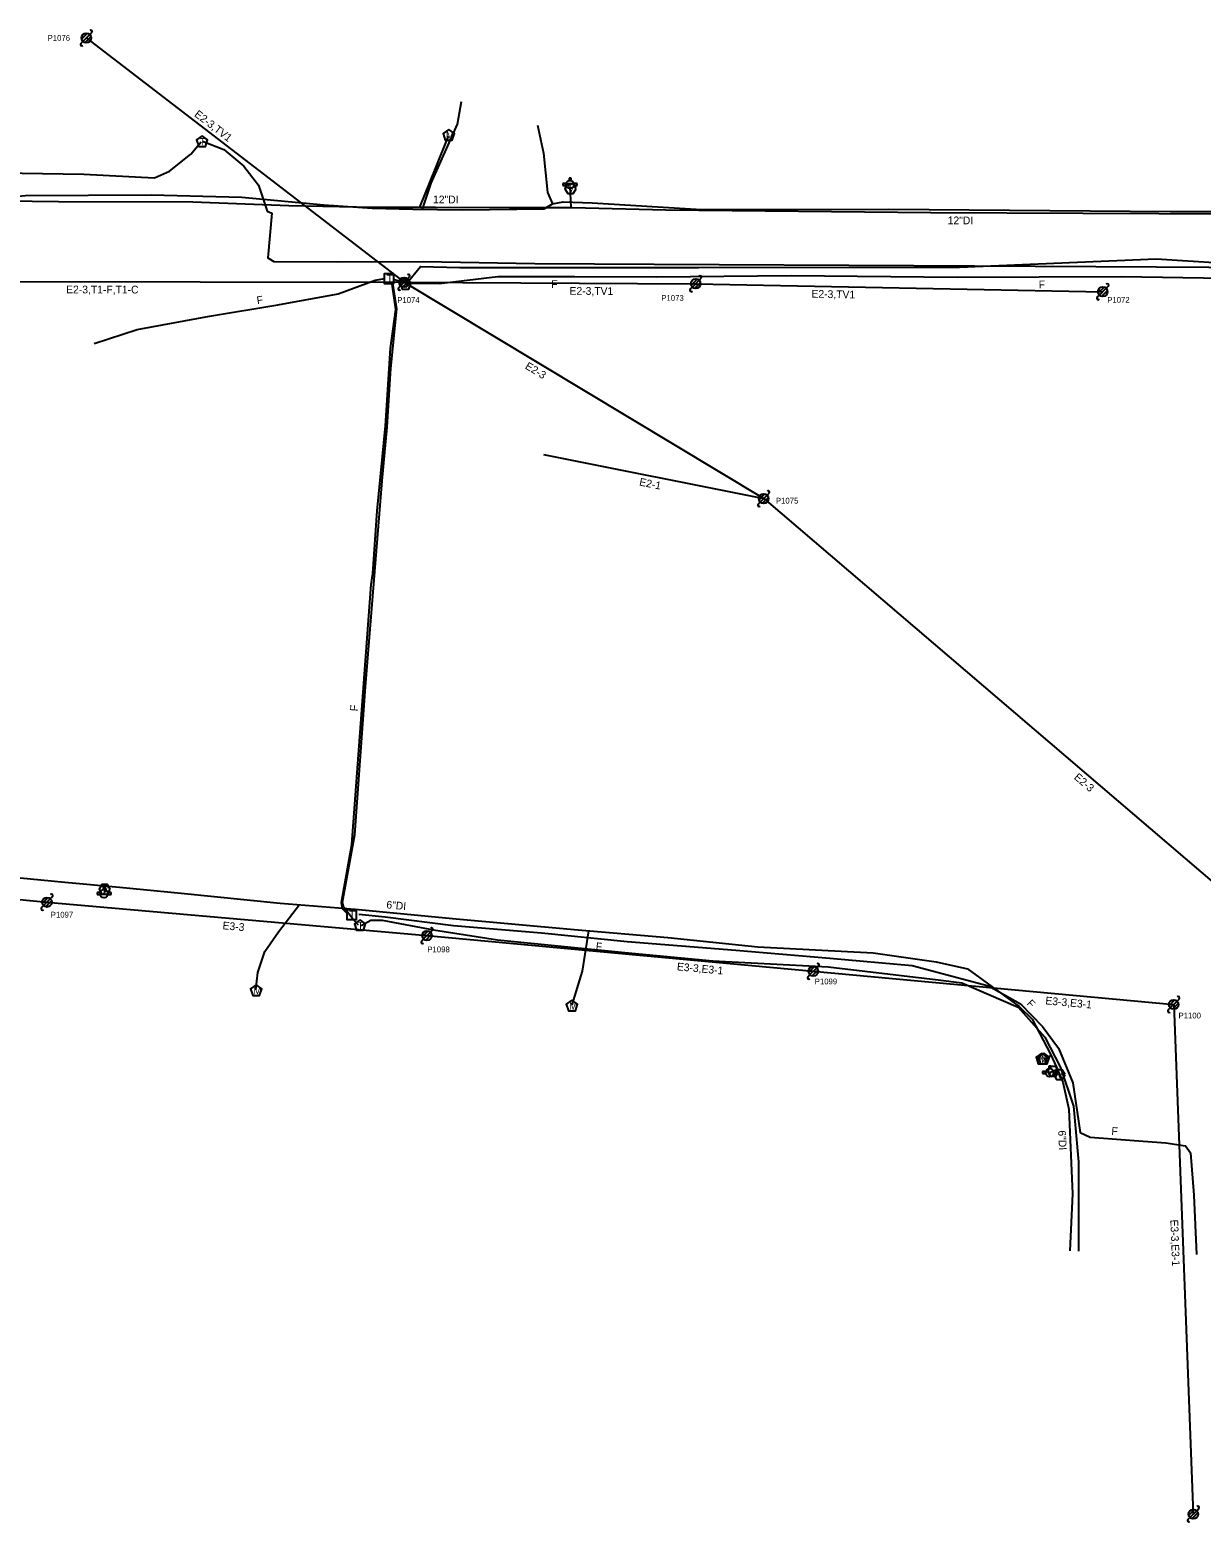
# Model space of a CAD drawing. Extents: x 1741604 to 1825760, y 1164229 to 1194908.
# Drawn here: x 1801773 to 1802379, y 1187603 to 1188375 of the extents above; entities that cross this region are included whole.
import ezdxf

# ---------------------------------------------------------------- set-up
doc = ezdxf.new("R2010")
doc.units = 0
for name, color, linetype in [('RD_EX_SU_Gas', 7, 'Continuous'), ('RD_EX_SU_H2O', 7, 'Continuous'), ('RD_EX_SU_Ovhd', 7, 'Continuous'), ('RD_EX_SU_Pole', 7, 'Continuous'), ('RD_EX_SU_Telecom', 7, 'Continuous'), ('RD_EX_SU_TX_H2O', 7, 'Continuous'), ('RD_EX_SU_TX_Pole', 7, 'Continuous'), ('RD_EX_SU_TX_Telecom', 7, 'Continuous')]:
    doc.layers.add(name, color=color, linetype=linetype)

# ---------------------------------------------------------------- blocks, each defined once
blk = doc.blocks.new('SUE_TPP')
at = {"layer": 'RD_EX_SU_Telecom'}
blk.add_lwpolyline([(0, 3), (-2.85, 0.93), (-1.76, -2.43), (1.76, -2.43), (2.85, 0.93)], close=True, dxfattribs=at)
blk.add_text('T', height=3.75, dxfattribs=at).set_placement((-1.25, -1.88))
blk = doc.blocks.new('SUE_WM')
at = {"layer": 'RD_EX_SU_H2O'}
blk.add_lwpolyline([(0, 3.05), (-2.9, 0.94), (-1.79, -2.47), (1.79, -2.47), (2.9, 0.94)], close=True, dxfattribs=at)
blk.add_text('M', height=3.75, dxfattribs=at).set_placement((-1.43, -1.88))
blk = doc.blocks.new('SUE_WV')
at = {"layer": 'RD_EX_SU_H2O'}
blk.add_lwpolyline([(2.89, 0), (1.44, 2.5), (-1.44, 2.5), (-2.89, 0), (-1.44, -2.5), (1.44, -2.5)], close=True, dxfattribs=at)
blk.add_text('V', height=3.75, dxfattribs=at).set_placement((-1.43, -1.88))
blk = doc.blocks.new('SUE_WFH')
at = {"layer": 'RD_EX_SU_H2O'}
for p, q in [((-2.01, 0.6), (-3.65, 0.6)), ((-3.65, 0.6), (-3.65, -0.45)), ((-0.48, 3.38), (-0.48, 2.04)), ((0.57, 3.38), (-0.48, 3.38)), ((0.57, 2.02), (0.57, 3.38)), ((3.7, 0.6), (2.01, 0.6)), ((3.7, -0.45), (3.7, 0.6)), ((-3.65, -0.45), (-2.05, -0.45)), ((2.05, -0.45), (3.7, -0.45))]:
    blk.add_line(p, q, dxfattribs=at)
for radius in [2.1, 0.263]:
    blk.add_circle((0, 0), radius, dxfattribs=at)
for start, end in [(163.3387, 192.31502), (74.24552, 103.21276), (347.68498, 16.6613)]:
    blk.add_arc((0, 0), 2.1, start, end, dxfattribs=at)
blk = doc.blocks.new('SUE_THH')
at = {"layer": 'RD_EX_SU_Telecom'}
blk.add_lwpolyline([(2.5, 2.5), (-2.5, 2.5), (-2.5, -2.5), (2.5, -2.5)], close=True, dxfattribs=at)
blk.add_text('T', height=4, dxfattribs=at).set_placement((-1.34, -2))
blk = doc.blocks.new('SUE_PP')
at = {"layer": 'RD_EX_SU_Pole'}
for p, q in [((-2.41, -0.65), (0.65, 2.41)), ((-1.77, -1.77), (1.77, 1.77)), ((-0.65, -2.41), (2.41, 0.65)), ((1.77, 1.77), (2.83, 2.83)), ((-2.83, -2.83), (-1.77, -1.77))]:
    blk.add_line(p, q, dxfattribs=at)
blk.add_circle((0, 0), 2.5, dxfattribs=at)
for centre, start, end in [((2.3, 3.36), 315, 135), ((-2.3, -3.36), 135, 315)]:
    blk.add_arc(centre, 0.75, start, end, dxfattribs=at)

msp = doc.modelspace()

# ---------------------------------------------------------------- linework, layer by layer
at = {"layer": 'RD_EX_SU_Gas'}
for points in [[(1801976.25, 1188282.13), (1801980.73, 1188295.55), (1801994.29, 1188326.19), (1801996.46, 1188337.93)], [(1802035.69, 1188325.53), (1802038.75, 1188311.1), (1802040.95, 1188290.73), (1802043.42, 1188284.85), (1802048.92, 1188285.96), (1802064.02, 1188285.5), (1802120.55, 1188282.05), (1802217.43, 1188282.09), (1802363.14, 1188281), (1802531.2, 1188280.89), (1802592.84, 1188280.65), (1802657.49, 1188281.38), (1802745.41, 1188285.57)], [(1801300.18, 1188289.75), (1801395.65, 1188290.16), (1801455.8, 1188291.53), (1801513.04, 1188289.66), (1801598.92, 1188288.81), (1801632.69, 1188288.87), (1801670.37, 1188289.16), (1801709.24, 1188288.32), (1801749.77, 1188287.36), (1801770.8, 1188289.23), (1801835.8, 1188289.57), (1801882.8, 1188288.37), (1801925.16, 1188284.33), (1801950.2, 1188282.64), (1801971.28, 1188282.21), (1801996.82, 1188281.83), (1802039.19, 1188282.29), (1802043.42, 1188284.85)]]:
    msp.add_lwpolyline(points, dxfattribs=at)
at = {"layer": 'RD_EX_SU_H2O'}
for p, q in [((1802052.46, 1188293.86), (1802053.04, 1188283.22)), ((1801811.94, 1187932.03), (1801811.71, 1187928.55)), ((1802297.91, 1187842.36), (1802301.39, 1187844.31)), ((1802304.72, 1187836.97), (1802301.07, 1187835.36))]:
    msp.add_line(p, q, dxfattribs=at)
for points in [[(1801974.9, 1188283.19), (1801982.97, 1188303.2), (1801989.64, 1188319.96)], [(1801299.98, 1188292.06), (1801348.52, 1188291.53), (1801396.06, 1188291.83), (1801455.82, 1188292.39), (1801499.16, 1188291.09), (1801533.71, 1188290.84), (1801614.7, 1188290.73), (1801629.95, 1188291.7), (1801670.47, 1188290.08), (1801698.41, 1188288.36), (1801733.35, 1188286.84), (1801787.88, 1188286.07), (1801857.46, 1188285.91)], [(1801857.46, 1188285.91), (1801907.01, 1188284.1), (1801950.85, 1188283.21), (1801982.92, 1188283.18), (1802021.22, 1188283.03), (1802053.57, 1188283.05), (1802102.06, 1188281.72), (1802239.26, 1188280.4), (1802593.05, 1188278.81), (1802731.51, 1188277.72), (1802853.5, 1188276.84), (1802894.3, 1188276.72), (1802928.34, 1188277.44), (1802964.61, 1188277.33), (1802990.65, 1188277.72), (1803038.29, 1188278.47)], [(1801725.3, 1187940.21), (1801791.08, 1187933.95), (1801819.37, 1187931.34), (1801851.29, 1187928.17), (1801902.56, 1187923.1), (1801941.32, 1187919.89), (1801991.7, 1187915.14), (1802054.62, 1187909.36), (1802103.14, 1187905.32), (1802149.67, 1187900.43), (1802209.38, 1187897.3), (1802242.04, 1187892.68), (1802258.1, 1187889), (1802284.97, 1187869.65), (1802291.6, 1187863.04), (1802301.1, 1187844.94), (1802304.23, 1187838.11), (1802307.56, 1187830.34), (1802310.63, 1187816.46), (1802312.45, 1187772.68), (1802311.13, 1187743.09)], [(1801889.94, 1187878.24), (1801891.06, 1187887.18), (1801894.69, 1187898.08), (1801901.75, 1187908.26), (1801912.64, 1187922.26)], [(1802053.72, 1187870.38), (1802059.06, 1187887.79), (1802062.28, 1187908.73)]]:
    msp.add_lwpolyline(points, dxfattribs=at)
at = {"layer": 'RD_EX_SU_Ovhd'}
for p, q in [((1801802.26, 1188370.75), (1801966.65, 1188244.29)), ((1801740.09, 1188244.68), (1801966.65, 1188244.29)), ((1801966.65, 1188244.29), (1802152.75, 1188132.38)), ((1801966.65, 1188244.29), (1802117.6, 1188243.55)), ((1802117.6, 1188243.55), (1802328.18, 1188239.42)), ((1802038.84, 1188155.18), (1802152.75, 1188132.38)), ((1802152.75, 1188132.38), (1802473.88, 1187858.09)), ((1801589.05, 1187942), (1801781.89, 1187923.55)), ((1801781.89, 1187923.55), (1801978.51, 1187906.27)), ((1801978.51, 1187906.27), (1802178.38, 1187887.81)), ((1802178.38, 1187887.81), (1802364.88, 1187870.6)), ((1802364.88, 1187870.6), (1802374.98, 1187606.9))]:
    msp.add_line(p, q, dxfattribs=at)
at = {"layer": 'RD_EX_SU_Pole'}
for p, q in [((1801963.82, 1188241.46), (1801964.88, 1188242.52)), ((1801964.24, 1188243.64), (1801967.3, 1188246.7)), ((1801964.88, 1188242.52), (1801968.42, 1188246.06)), ((1801966, 1188241.87), (1801969.07, 1188244.94)), ((1801968.42, 1188246.06), (1801969.48, 1188247.12)), ((1802114.77, 1188240.72), (1802115.83, 1188241.78)), ((1802115.18, 1188242.9), (1802118.24, 1188245.97)), ((1802115.83, 1188241.78), (1802119.36, 1188245.32)), ((1802116.95, 1188241.14), (1802120.01, 1188244.2)), ((1802119.36, 1188245.32), (1802120.42, 1188246.38)), ((1802150.33, 1188131.74), (1802153.39, 1188134.8)), ((1802150.98, 1188130.61), (1802154.51, 1188134.15)), ((1802154.51, 1188134.15), (1802155.57, 1188135.21)), ((1802149.92, 1188129.55), (1802150.98, 1188130.61)), ((1802152.1, 1188129.97), (1802155.16, 1188133.03)), ((1801779.47, 1187922.9), (1801782.53, 1187925.96)), ((1801780.12, 1187921.78), (1801783.65, 1187925.32)), ((1801783.65, 1187925.32), (1801784.71, 1187926.38)), ((1801779.06, 1187920.72), (1801780.12, 1187921.78)), ((1801781.24, 1187921.13), (1801784.3, 1187924.2)), ((1801975.68, 1187903.44), (1801976.74, 1187904.5)), ((1801976.09, 1187905.62), (1801979.15, 1187908.68)), ((1801976.74, 1187904.5), (1801980.28, 1187908.03)), ((1801977.86, 1187903.85), (1801980.92, 1187906.91)), ((1801980.28, 1187908.03), (1801981.34, 1187909.09)), ((1802175.97, 1187887.16), (1802179.03, 1187890.22)), ((1802176.62, 1187886.04), (1802180.15, 1187889.57)), ((1802177.74, 1187885.39), (1802180.8, 1187888.45)), ((1802180.15, 1187889.57), (1802181.21, 1187890.64)), ((1802175.55, 1187884.98), (1802176.62, 1187886.04)), ((1802362.46, 1187869.96), (1802365.53, 1187873.02)), ((1802363.11, 1187868.83), (1802366.65, 1187872.37)), ((1802364.23, 1187868.19), (1802367.29, 1187871.25)), ((1802366.65, 1187872.37), (1802367.71, 1187873.43)), ((1802362.05, 1187867.77), (1802363.11, 1187868.83))]:
    msp.add_line(p, q, dxfattribs=at)
for centre in [(1801966.65, 1188244.29), (1802117.6, 1188243.55), (1802152.75, 1188132.38), (1801781.89, 1187923.55), (1801978.51, 1187906.27), (1802178.38, 1187887.81), (1802364.88, 1187870.6)]:
    msp.add_circle(centre, 2.5, dxfattribs=at)
for centre, start, end in [((1801964.35, 1188240.93), 135, 315), ((1801968.95, 1188247.65), 315, 135), ((1802119.89, 1188246.91), 315, 135), ((1802115.3, 1188240.19), 135, 315), ((1802155.04, 1188135.74), 315, 135), ((1802150.45, 1188129.02), 135, 315), ((1801784.18, 1187926.91), 315, 135), ((1801779.59, 1187920.19), 135, 315), ((1801980.81, 1187909.62), 315, 135), ((1801976.21, 1187902.91), 135, 315), ((1802180.68, 1187891.17), 315, 135), ((1802176.08, 1187884.45), 135, 315), ((1802367.18, 1187873.96), 315, 135), ((1802362.58, 1187867.24), 135, 315)]:
    msp.add_arc(centre, 0.75, start, end, dxfattribs=at)
at = {"layer": 'RD_EX_SU_Telecom'}
for p, q in [((1801962.96, 1188230.57), (1801960.8, 1188243.81)), ((1801965.75, 1188244.36), (1801961.24, 1188245.76)), ((1801959.86, 1188199.71), (1801962.96, 1188230.57)), ((1801957.91, 1188169.31), (1801959.86, 1188199.71)), ((1801955.33, 1188141.64), (1801957.91, 1188169.31)), ((1801946.71, 1188034.96), (1801955.33, 1188141.64)), ((1801941.14, 1187958.4), (1801946.71, 1188034.96)), ((1801934.87, 1187923.59), (1801941.14, 1187958.4))]:
    msp.add_line(p, q, dxfattribs=at)
for points in [[(1801655.86, 1188347.6), (1801655.95, 1188329.98), (1801657.97, 1188328.39), (1801682.15, 1188336.73), (1801696.88, 1188334.16), (1801702.52, 1188318.42), (1801706.09, 1188310.43), (1801716.39, 1188304.98), (1801729.28, 1188302.18), (1801747.59, 1188301.03), (1801801.04, 1188300.2), (1801837.59, 1188298.33), (1801845.25, 1188301.81), (1801856.3, 1188310.58), (1801861.71, 1188317.02)], [(1801862.35, 1188317.37), (1801873.43, 1188312.99), (1801883.86, 1188304.45), (1801891.39, 1188294.55), (1801895.78, 1188281.09), (1801898.32, 1188280.05), (1801896.15, 1188256.89), (1801899.35, 1188255.07), (1801932.38, 1188254.92), (1801976.57, 1188255.02), (1802034.35, 1188254.03), (1802096.1, 1188253.61), (1802230.47, 1188252.94), (1802355.95, 1188252.37), (1802518.32, 1188251.31), (1802574.51, 1188250.38), (1802659.53, 1188249.82), (1802718.99, 1188248.54), (1802800.77, 1188248.26), (1802860.92, 1188247.72), (1802867.92, 1188245.53), (1802871.84, 1188241.03), (1802871.83, 1188230.11)], [(1801968.17, 1188243.8), (1801975.11, 1188252.56), (1801995.47, 1188251.98), (1802119.14, 1188251.93), (1802254.07, 1188252.11), (1802355.76, 1188256.39), (1802454.16, 1188250.22), (1802615.38, 1188248.45), (1802660.58, 1188248.77), (1802719.54, 1188247.91), (1802781.2, 1188247.75), (1802841.08, 1188246.91), (1802917.35, 1188246.59), (1802979.82, 1188247.18), (1803040.76, 1188247.99), (1803094.59, 1188247.87), (1803108.84, 1188247.38), (1803112.58, 1188243.21)], [(1801806.38, 1188212.57), (1801828.6, 1188219.82), (1801866.07, 1188226.7), (1801901.39, 1188232.66), (1801932.6, 1188238.34), (1801951.69, 1188245.35), (1801956.77, 1188246.33)], [(1801937.44, 1187917.57), (1801934.88, 1187920.04), (1801934.31, 1187923.33), (1801939.57, 1187953.46), (1801949.62, 1188087.86), (1801950.43, 1188093.68), (1801952.68, 1188125.99), (1801957.13, 1188170.02), (1801959.71, 1188210.28), (1801962.5, 1188230.28), (1801960.31, 1188244.49)], [(1801967.37, 1188243.92), (1801984.85, 1188243.7), (1802015.11, 1188247.25), (1802055.06, 1188247.37), (1802097.38, 1188247.06), (1802166.97, 1188247.83), (1802252.78, 1188247.03), (1802337.76, 1188247.32), (1802433.59, 1188245.79), (1802518.24, 1188245.41), (1802614.63, 1188244.32), (1802677.58, 1188242.3), (1802718.6, 1188243.19), (1802760.44, 1188243.9), (1802821.17, 1188242.63), (1802859.98, 1188240.47), (1802897.26, 1188239.34), (1802946.24, 1188239.68), (1802991.69, 1188241.06), (1803061.1, 1188241.67)], [(1801943.15, 1187911.68), (1801940.05, 1187915.08), (1801935.43, 1187920.72), (1801934.87, 1187923.59)], [(1801943.26, 1187917.31), (1801956.92, 1187915.93), (1801992.21, 1187911.53), (1802037.78, 1187907.69), (1802082.02, 1187903.16), (1802138.34, 1187898.66), (1802186.93, 1187894.54), (1802229.54, 1187890.84), (1802268.97, 1187880.25), (1802285.55, 1187871.03), (1802296.96, 1187859.25), (1802305.18, 1187847.93), (1802312.74, 1187830.07), (1802316.39, 1187804.37), (1802321.63, 1187802.03), (1802344.38, 1187800.31), (1802360.84, 1187798.96), (1802371, 1187797.45), (1802373.6, 1187793.77), (1802375.28, 1187771.94), (1802376.6, 1187741.29)], [(1801944.47, 1187911.54), (1801949.56, 1187914.18), (1801955.28, 1187914.2), (1801981.85, 1187909.26), (1802014.93, 1187904.08), (1802080.82, 1187897.51), (1802126.41, 1187893.16), (1802186.18, 1187890.03), (1802242.93, 1187883.44), (1802255.33, 1187881.83), (1802284.32, 1187869.29), (1802298.2, 1187853.66), (1802306.27, 1187838.08), (1802313.08, 1187817.98), (1802315.58, 1187789.19), (1802315.54, 1187742.93)]]:
    msp.add_lwpolyline(points, dxfattribs=at)

# ---------------------------------------------------------------- block references
at = {"layer": 'RD_EX_SU_H2O'}
for name, p in [('SUE_WM', (1801989.81, 1188320.35)), ('SUE_WFH', (1802052.53, 1188294.87)), ('SUE_WV', (1802052.8, 1188292.74)), ('SUE_WV', (1801811.77, 1187930.27)), ('SUE_WFH', (1801811.48, 1187927.93)), ('SUE_WM', (1801890.15, 1187877.76)), ('SUE_WM', (1802053.5, 1187869.85)), ('SUE_WM', (1802296.57, 1187842.45)), ('SUE_WM', (1802297.66, 1187842.34)), ('SUE_WFH', (1802300.68, 1187835.32)), ('SUE_WV', (1802302.49, 1187836.1)), ('SUE_WV', (1802305.75, 1187834.34))]:
    msp.add_blockref(name, p, dxfattribs=at)
at = {"layer": 'RD_EX_SU_Pole'}
for p in [(1801802.26, 1188370.75), (1802328.18, 1188239.42), (1802374.98, 1187606.9)]:
    msp.add_blockref('SUE_PP', p, dxfattribs=at)
at = {"layer": 'RD_EX_SU_Telecom'}
for name, p in [('SUE_TPP', (1801862.17, 1188317.04)), ('SUE_THH', (1801958.95, 1188246.21)), ('SUE_TPP', (1801967.46, 1188243.22)), ('SUE_THH', (1801939.58, 1187917.07)), ('SUE_TPP', (1801943.9, 1187911.44))]:
    msp.add_blockref(name, p, dxfattribs=at)

# ---------------------------------------------------------------- texts
at = {"layer": 'RD_EX_SU_Ovhd'}
for s, rotation, p in [('E2-3,TV1', 322.43088, (1801857.83, 1188330.53)), ('E2-3,T1-F,T1-C', 359.90156, (1801791.85, 1188238.59)), ('E2-3,TV1', 359.71986, (1802052.28, 1188237.87)), ('E2-3,TV1', 358.87692, (1802177.43, 1188236.38)), ('E2-3', 328.97973, (1802028.92, 1188199.85)), ('E2-1', 348.6846, (1802088.12, 1188139.2)), ('E2-3', 319.4977, (1802312.96, 1187987.65)), ('E3-3', 354.97657, (1801872.65, 1187909.55)), ('E3-3,E3-1', 354.72348, (1802107.7, 1187888.31)), ('E3-3,E3-1', 354.72927, (1802298.35, 1187870.71)), ('E3-3,E3-1', 272.19301, (1802363.14, 1187759.22))]:
    msp.add_text(s, height=4, rotation=rotation, dxfattribs=at).set_placement(p)
at = {"layer": 'RD_EX_SU_TX_H2O'}
for s, rotation, p in [('12"DI', 359.77683, (1801981.66, 1188285.18)), ('12"DI', 359.74357, (1802247.92, 1188274.36)), ('6"DI', 354.6207, (1801957.38, 1187920.38)), ('6"DI', 272.37936, (1802305.09, 1187805.37))]:
    msp.add_text(s, height=4, rotation=rotation, dxfattribs=at).set_placement(p)
at = {"layer": 'RD_EX_SU_TX_Pole'}
for s, p in [('P1076', (1801782.27, 1188369.24)), ('P1074', (1801963.14, 1188233.65)), ('P1073', (1802099.77, 1188234.71)), ('P1072', (1802330.49, 1188233.71)), ('P1075', (1802159.06, 1188129.8)), ('P1097', (1801783.89, 1187915.57)), ('P1098', (1801978.71, 1187897.6)), ('P1099', (1802179.15, 1187881.02)), ('P1100', (1802367.35, 1187863.38))]:
    msp.add_text(s, height=3, dxfattribs=at).set_placement(p)
at = {"layer": 'RD_EX_SU_TX_Telecom'}
for rotation, p in [(0.177, (1802042.86, 1188241.33)), (0.19749, (1802295.02, 1188241.18)), (9.58546, (1801890.78, 1188232.9)), (85.72311, (1801942.7, 1188022.22)), (354.15346, (1802065.71, 1187898.8)), (314.07868, (1802288.55, 1187870.81)), (355.67593, (1802332.52, 1187803.21))]:
    msp.add_text('F', height=4, rotation=rotation, dxfattribs=at).set_placement(p)

doc.saveas('drawing.dxf')
